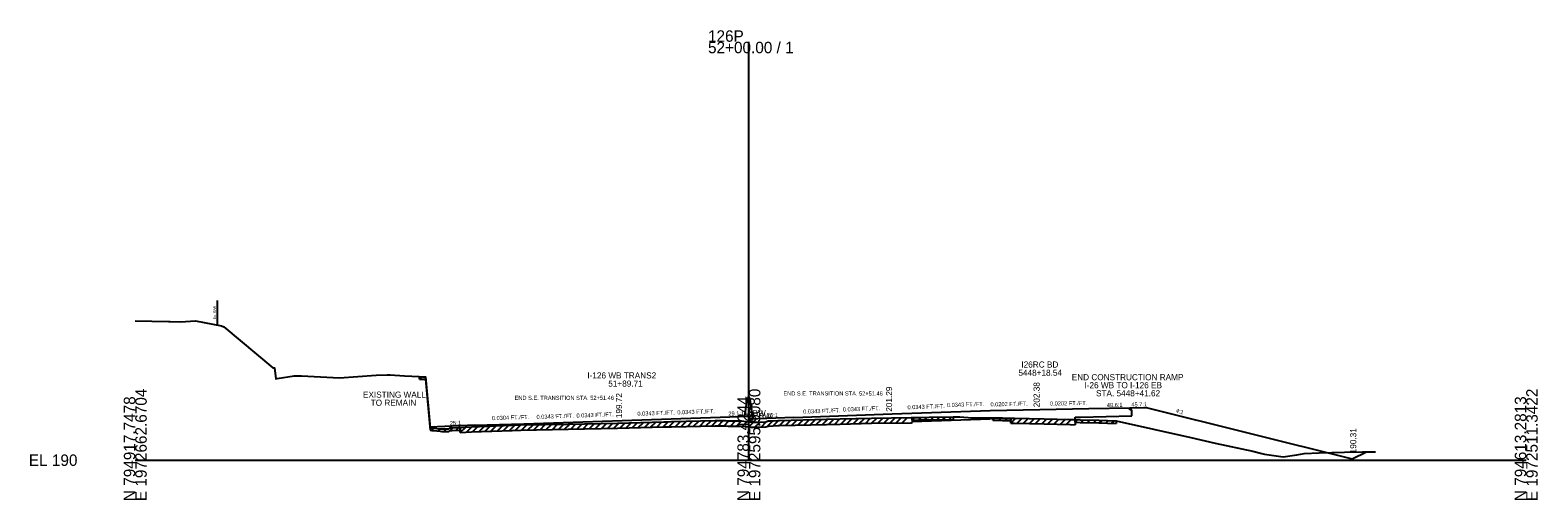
# Model space of a CAD drawing. Extents: x -161 to 1970889, y -4362 to 797231.
# Drawn here: x 1974.3 to 2342.8, y 4490.3 to 4605.1 of the extents above; entities that cross this region are included whole.
import ezdxf

# ---------------------------------------------------------------- set-up
doc = ezdxf.new("R2010")
doc.units = 0
for name, color, linetype in [('RD_GPK_XS_Cell', 7, 'Continuous'), ('RD_XS_Base', 7, 'Continuous'), ('RD_XS_EarthShd', 7, 'Continuous'), ('RD_XS_ExGround', 7, 'Continuous'), ('RD_XS_ExPaveRet', 7, 'Continuous'), ('RD_XS_ExRW', 7, 'Continuous'), ('RD_XS_MedBWall', 7, 'Continuous'), ('RD_XS_Misc_Line', 7, 'Continuous'), ('RD_XS_Pave', 7, 'Continuous'), ('RD_XS_PaveOvlay', 7, 'Continuous'), ('RD_XS_PaveShd', 7, 'Continuous'), ('RD_XS_TieSlope', 7, 'Continuous'), ('RD_XS_TX_Elev_EX', 7, 'Continuous'), ('RD_XS_TX_Elev_PR', 7, 'Continuous'), ('RD_XS_TX_Misc', 7, 'Continuous'), ('RD_XS_TX_MkPT', 7, 'Continuous'), ('RD_XS_TX_Notes', 7, 'Continuous'), ('RD_XS_TX_Profile', 7, 'Continuous'), ('RD_XS_TX_ShdSlope', 7, 'Continuous'), ('RD_XS_TX_Slope', 7, 'Continuous'), ('RD_XS_TX_Station', 7, 'Continuous')]:
    doc.layers.add(name, color=color, linetype=linetype)

msp = doc.modelspace()

# ---------------------------------------------------------------- linework, layer by layer
at = {"layer": 'RD_GPK_XS_Cell'}
for p, q in [((2150, 4500), (2150, 4602.26)), ((2000, 4500), (2150, 4500)), ((2150, 4500), (2340, 4500))]:
    msp.add_line(p, q, dxfattribs=at)
at = {"layer": 'RD_XS_Base'}
for p, q in [((2243.07, 4512.27), (2243.07, 4512.83)), ((2243.57, 4512.28), (2243.07, 4512.27)), ((2243.57, 4510.8), (2243.57, 4512.28)), ((2189.93, 4509.42), (2209, 4510.08)), ((2214.06, 4510.19), (2209, 4510.08)), ((2229.72, 4510.52), (2231.07, 4510.54)), ((2231.07, 4510.54), (2243.57, 4510.8))]:
    msp.add_line(p, q, dxfattribs=at)
at = {"layer": 'RD_XS_EarthShd'}
msp.add_line((2243.07, 4512.83), (2247.08, 4512.91), dxfattribs=at)
at = {"layer": 'RD_XS_ExGround'}
msp.add_line((2300, 4502.05), (2303.19, 4502.08), dxfattribs=at)
msp.add_lwpolyline([(2000, 4534.08), (2008.12, 4533.89), (2008.54, 4533.88), (2011.05, 4533.82), (2014.7, 4534.09), (2021.06, 4532.81), (2021.61, 4532.56), (2033.64, 4522.6), (2034.02, 4522.6), (2034.35, 4519.91), (2034.68, 4519.97), (2038.83, 4520.63), (2040.65, 4520.58), (2049.96, 4520.15), (2058.92, 4520.77), (2061.58, 4520.9), (2062.29, 4520.88), (2065.81, 4520.59), (2069.36, 4520.42), (2070.17, 4520.41), (2070.94, 4520.41), (2072.05, 4507.93), (2072.5, 4507.89), (2072.93, 4507.85), (2074.52, 4507.68), (2074.97, 4507.63), (2076.63, 4507.66), (2076.87, 4507.87), (2077.5, 4507.9), (2082.18, 4508.14), (2092.1, 4508.52), (2094.27, 4508.6), (2105.78, 4508.83), (2117.91, 4509.07), (2129.23, 4509.37), (2130.09, 4509.39), (2131.04, 4509.42), (2141.77, 4509.67), (2143.68, 4509.68), (2144.24, 4509.68), (2144.9, 4509.59), (2145.55, 4509.59), (2148.18, 4509.6), (2150, 4509.4), (2150.47, 4509.35), (2150.92, 4509.29), (2152.62, 4509.33), (2154.17, 4509.38), (2154.73, 4509.6), (2155.9, 4509.65), (2157.09, 4509.69), (2157.44, 4509.7), (2168.97, 4510), (2172.31, 4510.08), (2179.95, 4510.27), (2189.66, 4510.41), (2192.02, 4510.45), (2194.07, 4510.49), (2199.93, 4510.57), (2201.53, 4510.59), (2204.54, 4510.39), (2206.29, 4510.32), (2208.63, 4510.35), (2209.61, 4510.37), (2212.01, 4510.34), (2214.12, 4510.31), (2214.92, 4510.29), (2222.14, 4510.13), (2228.52, 4509.94), (2230.96, 4509.88), (2235.5, 4509.74), (2239.73, 4509.6), (2258, 4505.52), (2263.98, 4504.18), (2273.18, 4502.2), (2275.36, 4501.62), (2276.02, 4501.51), (2280.56, 4500.82), (2283.96, 4501.34), (2285.76, 4501.62), (2289.35, 4501.77), (2295.56, 4502), (2300, 4502.05)], dxfattribs=at)
at = {"layer": 'RD_XS_ExPaveRet'}
for p, q in [((2069.45, 4519.8), (2069.45, 4520.42)), ((2069.45, 4519.8), (2070.17, 4519.78)), ((2070.17, 4519.78), (2070.94, 4519.78)), ((2070.94, 4519.78), (2072.05, 4507.3)), ((2072.05, 4507.3), (2072.5, 4507.27)), ((2072.5, 4507.27), (2072.93, 4507.23)), ((2072.93, 4507.23), (2074.52, 4507.06)), ((2076.63, 4507.04), (2076.87, 4507.24)), ((2076.87, 4507.24), (2077.5, 4507.27)), ((2077.5, 4507.27), (2079.45, 4507.37)), ((2079.45, 4506.75), (2079.45, 4508)), ((2079.45, 4508), (2079.45, 4507.37)), ((2082.18, 4506.89), (2092.1, 4507.27)), ((2092.1, 4507.27), (2094.27, 4507.35)), ((2094.27, 4507.35), (2105.78, 4507.58)), ((2105.78, 4507.58), (2117.91, 4507.82)), ((2117.91, 4507.82), (2129.23, 4508.12)), ((2129.23, 4508.12), (2130.09, 4508.14)), ((2130.09, 4508.14), (2131.04, 4508.17)), ((2131.04, 4508.17), (2141.77, 4508.42)), ((2141.77, 4508.42), (2143.68, 4508.43)), ((2143.68, 4508.43), (2144.24, 4508.43)), ((2144.24, 4508.43), (2144.9, 4508.34)), ((2144.9, 4508.34), (2145.55, 4508.34)), ((2145.55, 4508.34), (2148.18, 4508.35)), ((2148.18, 4508.35), (2150, 4508.15)), ((2150, 4508.15), (2150.47, 4508.1)), ((2150.47, 4508.1), (2150.92, 4508.04)), ((2150.92, 4508.04), (2152.62, 4508.08)), ((2152.62, 4508.08), (2154.17, 4508.13)), ((2154.17, 4508.13), (2154.73, 4508.35)), ((2154.73, 4508.35), (2155.9, 4508.4)), ((2155.9, 4508.4), (2157.09, 4508.44)), ((2157.09, 4508.44), (2157.44, 4508.45)), ((2157.44, 4508.45), (2168.97, 4508.75)), ((2168.97, 4508.75), (2172.31, 4508.83)), ((2172.31, 4508.83), (2179.95, 4509.02)), ((2179.95, 4509.02), (2189.66, 4509.16)), ((2189.66, 4509.16), (2189.93, 4509.17)), ((2189.93, 4510.42), (2189.93, 4509.17)), ((2189.93, 4509.79), (2189.93, 4510.42)), ((2189.93, 4509.79), (2192.02, 4509.83)), ((2192.02, 4509.83), (2194.07, 4509.86)), ((2194.07, 4509.86), (2199.93, 4509.94)), ((2199.93, 4510.57), (2199.93, 4509.94)), ((2209.61, 4509.74), (2209.61, 4510.37)), ((2209.61, 4509.74), (2212.01, 4509.71)), ((2212.01, 4509.71), (2214.06, 4509.68)), ((2214.06, 4509.06), (2214.06, 4510.31)), ((2214.06, 4510.31), (2214.06, 4509.68)), ((2214.06, 4509.06), (2214.12, 4509.06)), ((2214.12, 4509.06), (2214.92, 4509.04)), ((2214.92, 4509.04), (2222.14, 4508.88)), ((2222.14, 4508.88), (2228.52, 4508.69)), ((2228.52, 4508.69), (2229.72, 4508.66)), ((2229.72, 4509.91), (2229.72, 4508.66)), ((2229.72, 4509.28), (2229.72, 4509.91)), ((2229.72, 4509.28), (2230.96, 4509.25)), ((2230.96, 4509.25), (2235.5, 4509.12)), ((2235.5, 4509.12), (2239.73, 4508.98)), ((2239.73, 4509.6), (2239.73, 4508.98)), ((2074.52, 4507.06), (2074.97, 4507.01)), ((2074.97, 4507.01), (2076.63, 4507.04)), ((2079.45, 4506.75), (2082.18, 4506.89))]:
    msp.add_line(p, q, dxfattribs=at)
at = {"layer": 'RD_XS_ExRW'}
msp.add_line((2020, 4539.02), (2020, 4533.02), dxfattribs=at)
at = {"layer": 'RD_XS_MedBWall'}
for p, q in [((2149, 4510.75), (2149.67, 4515.28)), ((2150.22, 4515.28), (2149.67, 4515.28)), ((2151, 4510.07), (2150.22, 4515.28))]:
    msp.add_line(p, q, dxfattribs=at)
at = {"layer": 'RD_XS_Misc_Line'}
for p, q in [((2069.45, 4519.8), (2070.06, 4520.41)), ((2070.95, 4519.65), (2071, 4519.7)), ((2072.45, 4507.27), (2073.02, 4507.84)), ((2073.95, 4507.12), (2074.51, 4507.68)), ((2075.45, 4507.01), (2076.09, 4507.65)), ((2076.95, 4507.25), (2077.61, 4507.9)), ((2078.45, 4507.32), (2079.11, 4507.98)), ((2079.45, 4506.75), (2080.77, 4508.06)), ((2080.95, 4506.82), (2082.27, 4508.14)), ((2082.45, 4506.9), (2083.75, 4508.2)), ((2083.95, 4506.95), (2085.25, 4508.25)), ((2085.45, 4507.01), (2086.75, 4508.31)), ((2086.95, 4507.07), (2088.25, 4508.37)), ((2088.45, 4507.13), (2089.75, 4508.43)), ((2089.95, 4507.19), (2091.25, 4508.49)), ((2091.45, 4507.24), (2092.75, 4508.54)), ((2092.95, 4507.3), (2094.25, 4508.6)), ((2094.45, 4507.35), (2095.73, 4508.63)), ((2095.95, 4507.38), (2097.23, 4508.66)), ((2097.45, 4507.41), (2098.73, 4508.69)), ((2098.95, 4507.44), (2100.23, 4508.72)), ((2100.45, 4507.47), (2101.73, 4508.75)), ((2101.95, 4507.5), (2103.23, 4508.78)), ((2103.45, 4507.53), (2104.73, 4508.81)), ((2104.95, 4507.56), (2106.23, 4508.83)), ((2106.46, 4507.59), (2107.73, 4508.87)), ((2107.96, 4507.62), (2109.23, 4508.9)), ((2109.46, 4507.65), (2110.73, 4508.93)), ((2110.96, 4507.68), (2112.23, 4508.96)), ((2112.46, 4507.71), (2113.73, 4508.99)), ((2113.96, 4507.74), (2115.23, 4509.02)), ((2115.46, 4507.77), (2116.73, 4509.05)), ((2116.96, 4507.8), (2118.24, 4509.08)), ((2118.46, 4507.84), (2119.74, 4509.12)), ((2119.96, 4507.88), (2121.24, 4509.16)), ((2121.46, 4507.92), (2122.74, 4509.2)), ((2122.96, 4507.96), (2124.24, 4509.24)), ((2124.46, 4507.99), (2125.74, 4509.28)), ((2125.96, 4508.03), (2127.24, 4509.32)), ((2127.46, 4508.07), (2128.74, 4509.36)), ((2128.96, 4508.11), (2130.24, 4509.4)), ((2130.46, 4508.15), (2131.74, 4509.43)), ((2131.96, 4508.19), (2133.24, 4509.47)), ((2133.46, 4508.22), (2134.74, 4509.5)), ((2134.96, 4508.26), (2136.24, 4509.54)), ((2136.46, 4508.29), (2137.74, 4509.57)), ((2137.96, 4508.33), (2139.24, 4509.61)), ((2139.46, 4508.36), (2140.74, 4509.64)), ((2140.96, 4508.4), (2142.23, 4509.67)), ((2142.46, 4508.42), (2143.72, 4509.68)), ((2143.96, 4508.43), (2145.12, 4509.59)), ((2145.46, 4508.34), (2146.72, 4509.59)), ((2146.96, 4508.34), (2148.21, 4509.6)), ((2148.46, 4508.32), (2149.59, 4509.44)), ((2149.96, 4508.15), (2151.1, 4509.29)), ((2151.46, 4508.05), (2152.75, 4509.33)), ((2152.96, 4508.09), (2154.3, 4509.43)), ((2154.46, 4508.24), (2155.87, 4509.65)), ((2155.96, 4508.4), (2157.26, 4509.7)), ((2157.47, 4508.45), (2158.75, 4509.74)), ((2158.97, 4508.49), (2160.25, 4509.78)), ((2160.47, 4508.53), (2161.75, 4509.81)), ((2161.97, 4508.57), (2163.25, 4509.85)), ((2163.47, 4508.61), (2164.75, 4509.89)), ((2164.97, 4508.65), (2166.25, 4509.93)), ((2166.47, 4508.69), (2167.75, 4509.97)), ((2167.97, 4508.73), (2169.25, 4510.01)), ((2169.47, 4508.76), (2170.75, 4510.04)), ((2170.97, 4508.8), (2172.25, 4510.08)), ((2172.47, 4508.83), (2173.75, 4510.12)), ((2173.97, 4508.87), (2175.25, 4510.15)), ((2175.47, 4508.91), (2176.75, 4510.19)), ((2176.97, 4508.94), (2178.25, 4510.22)), ((2178.47, 4508.98), (2179.75, 4510.26)), ((2179.97, 4509.02), (2181.24, 4510.29)), ((2181.47, 4509.04), (2182.74, 4510.31)), ((2182.97, 4509.06), (2184.24, 4510.33)), ((2184.47, 4509.08), (2185.74, 4510.35)), ((2185.97, 4509.11), (2187.24, 4510.38)), ((2187.47, 4509.13), (2188.74, 4510.4)), ((2189.93, 4509.79), (2190.56, 4510.43)), ((2191.43, 4509.82), (2192.06, 4510.45)), ((2192.93, 4509.84), (2193.57, 4510.48)), ((2194.43, 4509.87), (2195.06, 4510.5)), ((2195.93, 4509.89), (2196.56, 4510.52)), ((2197.43, 4509.91), (2198.06, 4510.54)), ((2198.93, 4509.93), (2199.56, 4510.56)), ((2209.61, 4509.74), (2210.23, 4510.36)), ((2211.11, 4509.72), (2211.73, 4510.34)), ((2212.61, 4509.7), (2213.23, 4510.32)), ((2214.06, 4509.06), (2215.28, 4510.28)), ((2215.56, 4509.03), (2216.78, 4510.25)), ((2217.06, 4508.99), (2218.28, 4510.22)), ((2218.56, 4508.96), (2219.78, 4510.18)), ((2220.06, 4508.93), (2221.28, 4510.15)), ((2221.56, 4508.89), (2222.78, 4510.11)), ((2223.06, 4508.85), (2224.27, 4510.07)), ((2224.56, 4508.81), (2225.77, 4510.02)), ((2226.06, 4508.76), (2227.27, 4509.98)), ((2227.56, 4508.72), (2228.77, 4509.93)), ((2229.72, 4509.28), (2230.33, 4509.89)), ((2231.22, 4509.25), (2231.83, 4509.85)), ((2232.72, 4509.2), (2233.33, 4509.81)), ((2234.22, 4509.16), (2234.83, 4509.76)), ((2235.72, 4509.11), (2236.33, 4509.72)), ((2237.23, 4509.06), (2237.83, 4509.67)), ((2238.73, 4509.01), (2239.33, 4509.62))]:
    msp.add_line(p, q, dxfattribs=at)
at = {"layer": 'RD_XS_Pave'}
for p, q in [((2161, 4510.47), (2185, 4511.29)), ((2185, 4511.29), (2209, 4512.12)), ((2209, 4512.12), (2221.07, 4512.38)), ((2221.07, 4512.38), (2233.07, 4512.62)), ((2082.99, 4508.53), (2094.99, 4508.9)), ((2094.99, 4508.9), (2118.99, 4509.72)), ((2118.99, 4509.72), (2142.99, 4510.54))]:
    msp.add_line(p, q, dxfattribs=at)
at = {"layer": 'RD_XS_PaveOvlay'}
for p, q in [((2079.45, 4508), (2082.18, 4508.14)), ((2082.18, 4508.14), (2092.1, 4508.52)), ((2092.1, 4508.52), (2094.27, 4508.6)), ((2094.27, 4508.6), (2105.78, 4508.83)), ((2105.78, 4508.83), (2117.91, 4509.07)), ((2117.91, 4509.07), (2129.23, 4509.37)), ((2129.23, 4509.37), (2130.09, 4509.39)), ((2130.09, 4509.39), (2131.04, 4509.42)), ((2131.04, 4509.42), (2141.77, 4509.67)), ((2141.77, 4509.67), (2143.68, 4509.68)), ((2143.68, 4509.68), (2144.24, 4509.68)), ((2144.24, 4509.68), (2144.9, 4509.59)), ((2144.9, 4509.59), (2145.55, 4509.59)), ((2145.55, 4509.59), (2148.18, 4509.6)), ((2148.18, 4509.6), (2150, 4509.4)), ((2150, 4509.4), (2150.47, 4509.35)), ((2150.47, 4509.35), (2150.92, 4509.29)), ((2150.92, 4509.29), (2152.62, 4509.33)), ((2152.62, 4509.33), (2154.17, 4509.38)), ((2154.17, 4509.38), (2154.73, 4509.6)), ((2154.73, 4509.6), (2155.9, 4509.65)), ((2155.9, 4509.65), (2157.09, 4509.69)), ((2157.09, 4509.69), (2157.44, 4509.7)), ((2157.44, 4509.7), (2168.97, 4510)), ((2168.97, 4510), (2172.31, 4510.08)), ((2172.31, 4510.08), (2179.95, 4510.27)), ((2179.95, 4510.27), (2189.66, 4510.41)), ((2189.66, 4510.41), (2189.93, 4510.42)), ((2189.93, 4510.42), (2189.93, 4509.42)), ((2214.06, 4510.31), (2214.92, 4510.29)), ((2214.06, 4510.31), (2214.06, 4510.19)), ((2214.92, 4510.29), (2218.53, 4510.21)), ((2218.53, 4510.21), (2222.14, 4510.13)), ((2222.14, 4510.13), (2225.33, 4510.04)), ((2225.33, 4510.04), (2228.52, 4509.94)), ((2228.52, 4509.94), (2229.72, 4509.91)), ((2229.72, 4509.91), (2229.72, 4510.52))]:
    msp.add_line(p, q, dxfattribs=at)
msp.add_lwpolyline([(2072.04, 4508.09), (2072.05, 4507.93), (2072.5, 4507.89), (2072.93, 4507.85), (2074.52, 4507.68), (2074.97, 4507.63), (2076.63, 4507.66), (2076.87, 4507.87), (2077.5, 4507.9), (2079.45, 4508)], dxfattribs=at)
at = {"layer": 'RD_XS_PaveShd'}
for p, q in [((2233.07, 4512.62), (2243.07, 4512.83)), ((2082.99, 4508.53), (2072.04, 4508.09)), ((2142.99, 4510.54), (2150, 4510.78)), ((2150, 4510.03), (2150, 4510.78)), ((2161, 4510.47), (2150, 4510.03))]:
    msp.add_line(p, q, dxfattribs=at)
at = {"layer": 'RD_XS_TieSlope'}
for p, q in [((2247.08, 4512.91), (2297.49, 4500.31)), ((2297.49, 4500.31), (2300.98, 4502.06))]:
    msp.add_line(p, q, dxfattribs=at)

# ---------------------------------------------------------------- texts
at = {"layer": 'RD_GPK_XS_Cell'}
for s, p in [('126P', (2140, 4602.26)), ('52+00.00 / 1', (2140, 4599.46)), ('EL 190', (1974, 4498.6))]:
    msp.add_text(s, height=2.8, dxfattribs=at).set_placement(p)
for s, p in [('N 794917.7478', (2000, 4490)), ('E 1972662.6704', (2002.8, 4490)), ('N 794783.4244', (2150, 4490)), ('E 1972595.9080', (2152.8, 4490)), ('N 794613.2813', (2340, 4490)), ('E 1972511.3422', (2342.8, 4490))]:
    msp.add_text(s, height=2.8, rotation=90, dxfattribs=at).set_placement(p)
at = {"layer": 'RD_XS_ExRW'}
msp.add_text('Ex. R/W ', height=0.65, rotation=90, dxfattribs=at).set_placement((2019.75, 4534.41))
at = {"layer": 'RD_XS_TX_Elev_EX'}
msp.add_text('199.40', height=1, rotation=90, dxfattribs=at).set_placement((2151, 4509.4))
at = {"layer": 'RD_XS_TX_Elev_PR'}
for s, p in [(' 202.38', (2221.07, 4512.38)), (' 199.72', (2118.99, 4509.72)), (' 201.29', (2185, 4511.29))]:
    msp.add_text(s, height=1.5, rotation=90, dxfattribs=at).set_placement(p)
at = {"layer": 'RD_XS_TX_Misc'}
msp.add_text('190.31', height=1.5, rotation=90, dxfattribs=at).set_placement((2298.46, 4501.68))
at = {"layer": 'RD_XS_TX_MkPT'}
for s, p in [('WBW', (2149, 4510.75)), ('EBW', (2151, 4510.07))]:
    msp.add_text(s, height=1.5, dxfattribs=at).set_placement(p)
at = {"layer": 'RD_XS_TX_Notes'}
for s, height, p in [('END CONSTRUCTION RAMP', 1.5, (2228.91, 4519.54)), ('I-26 WB TO I-126 EB', 1.5, (2232.02, 4517.58)), ('EXISTING WALL', 1.5, (2055.66, 4515.27)), ('TO REMAIN', 1.5, (2057.55, 4513.3)), ('END S.E. TRANSITION STA. 52+51.46', 1, (2092.72, 4514.74)), ('END S.E. TRANSITION STA. 52+51.46', 1, (2158.43, 4515.81)), ('STA. 5448+41.62', 1.5, (2234.84, 4515.61))]:
    msp.add_text(s, height=height, dxfattribs=at).set_placement(p)
at = {"layer": 'RD_XS_TX_Profile'}
for s, rotation, p in [('29.1:1', 1.9651, (2145, 4510.86)), ('25:1', 2.2906, (2154.44, 4510.46)), ('49.6:1', 1.156, (2237.49, 4512.96)), ('25:1', 2.2906, (2076.92, 4508.54))]:
    msp.add_text(s, height=1, rotation=rotation, dxfattribs=at).set_placement(p)
at = {"layer": 'RD_XS_TX_ShdSlope'}
msp.add_text('45.7:1', height=1, rotation=1.2522, dxfattribs=at).set_placement((2243.49, 4513.09))
at = {"layer": 'RD_XS_TX_Slope'}
for s, rotation, p in [('0.0304 FT./FT.', 1.7428, (2087.18, 4509.78)), ('0.0343 FT./FT.', 1.9651, (2098.1, 4510.07)), ('0.0343 FT./FT.', 1.9651, (2107.86, 4510.4)), ('0.0343 FT./FT.', 1.9651, (2122.76, 4510.85)), ('0.0343 FT./FT.', 1.9651, (2132.52, 4511.18)), ('0.0343 FT./FT.', 1.9642, (2163.28, 4511.37)), ('0.0343 FT./FT.', 1.9642, (2172.97, 4511.88)), ('0.0343 FT./FT.', 1.9642, (2188.77, 4512.42)), ('0.0343 FT./FT.', 1.9642, (2198.41, 4512.96)), ('0.0202 FT./FT.', 1.156, (2209.05, 4513.14)), ('0.0202 FT./FT.', 1.156, (2223.59, 4513.33)), ('4:1', 344.1175, (2254.26, 4511.69))]:
    msp.add_text(s, height=1, rotation=rotation, dxfattribs=at).set_placement(p)
at = {"layer": 'RD_XS_TX_Station'}
for s, p in [('5448+18.54', (2215.87, 4520.63)), ('I26RC BD', (2216.6, 4522.63)), ('I-126 WB TRANS2', (2110.5, 4519.97)), ('51+89.71', (2115.62, 4517.97))]:
    msp.add_text(s, height=1.5, dxfattribs=at).set_placement(p)

doc.saveas('drawing.dxf')
